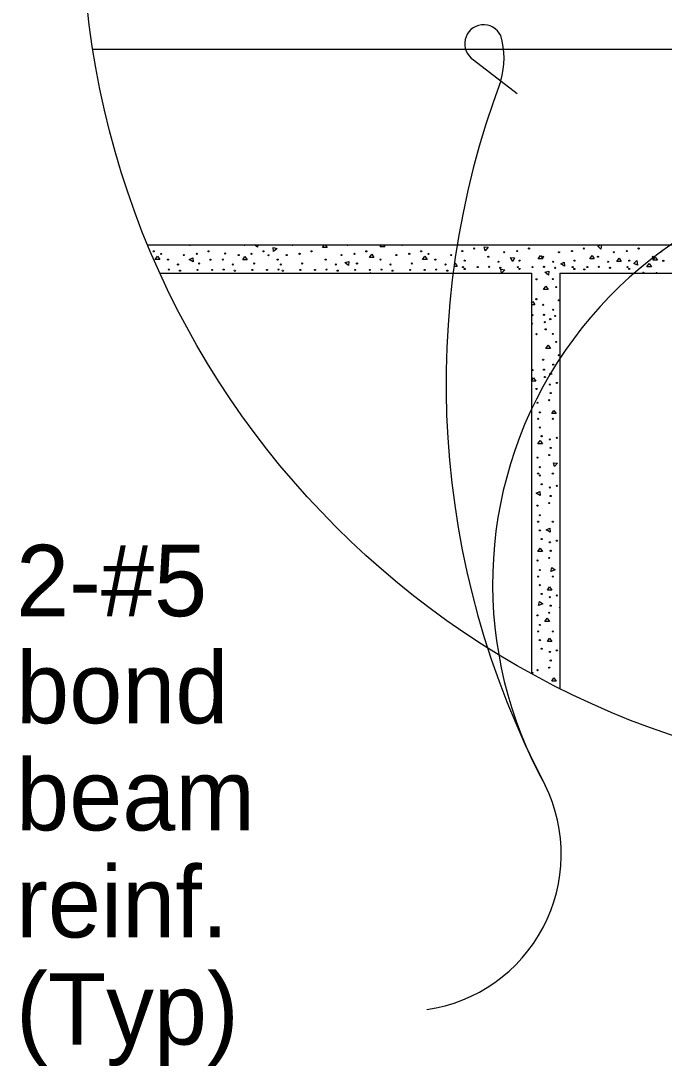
# Model space of a CAD drawing. Extents: x 0 to 2.83, y -0.03 to 1.83.
# Drawn here: x 0.6673 to 0.7845, y 0.1655 to 0.3561 of the extents above; entities that cross this region are included whole.
import ezdxf

# ---------------------------------------------------------------- set-up
doc = ezdxf.new("R2010")
doc.units = 0
for name, color, linetype in [('50', 7, 'Continuous'), ('51', 7, 'Continuous'), ('55', 7, 'Continuous'), ('57', 7, 'Continuous')]:
    doc.layers.add(name, color=color, linetype=linetype)

msp = doc.modelspace()

# ---------------------------------------------------------------- linework, layer by layer
at = {"layer": '50'}
for p, q in [((0.6903703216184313, 0.3153115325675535), (0.8714627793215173, 0.3153115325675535)), ((0.6926287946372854, 0.3101031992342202), (0.7603516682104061, 0.3101031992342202)), ((0.7655600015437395, 0.3101031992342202), (0.8714627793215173, 0.3101031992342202))]:
    msp.add_line(p, q, dxfattribs=at)
at = {"layer": '51'}
msp.add_line((0.8436961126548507, 0.35089625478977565), (0.680379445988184, 0.35089625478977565), dxfattribs=at)
at = {"layer": '55'}
for p, q in [((0.7498127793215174, 0.349004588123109), (0.7577627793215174, 0.342879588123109)), ((0.7603516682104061, 0.3101031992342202), (0.7603516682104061, 0.23710464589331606)), ((0.7655600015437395, 0.3101031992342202), (0.7655600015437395, 0.23437025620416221))]:
    msp.add_line(p, q, dxfattribs=at)
for points in [[(0.7104353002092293, 0.3153115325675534), (0.7103938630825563, 0.31485357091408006), (0.7098481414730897, 0.3153115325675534)], [(0.7133317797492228, 0.3140681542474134), (0.7132659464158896, 0.3147947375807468), (0.7139701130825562, 0.31460382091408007), (0.7133317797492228, 0.3140681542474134)], [(0.7222735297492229, 0.3147827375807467), (0.7226414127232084, 0.3153115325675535)], [(0.7227389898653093, 0.3153115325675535), (0.7231069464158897, 0.3147827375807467), (0.7222735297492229, 0.3147827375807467)], [(0.7327846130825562, 0.3149469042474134), (0.7330382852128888, 0.3153115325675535)], [(0.7333643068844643, 0.3153115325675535), (0.7336180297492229, 0.3149469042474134), (0.7327846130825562, 0.3149469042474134)], [(0.751910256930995, 0.31420630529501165), (0.7517193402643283, 0.3149103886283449), (0.7524460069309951, 0.31484472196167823), (0.751910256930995, 0.31420630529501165)], [(0.7730096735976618, 0.3145155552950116), (0.772492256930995, 0.3150299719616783), (0.7731008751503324, 0.3153115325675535)], [(0.7731500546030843, 0.3153115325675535), (0.7730096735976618, 0.3145155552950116)], [(0.6917425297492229, 0.31260657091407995), (0.6921591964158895, 0.3132054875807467), (0.6925759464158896, 0.31260657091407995), (0.6917425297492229, 0.31260657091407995)], [(0.6979428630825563, 0.31262565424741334), (0.6986031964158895, 0.3129359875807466), (0.6986646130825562, 0.31220890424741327), (0.6979428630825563, 0.31262565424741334)], [(0.7076991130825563, 0.31256023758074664), (0.708115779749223, 0.31315915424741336), (0.7085325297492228, 0.31256023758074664), (0.7076991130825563, 0.31256023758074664)], [(0.7308100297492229, 0.31297732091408), (0.7312266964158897, 0.31357623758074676), (0.7316434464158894, 0.31297732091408), (0.7308100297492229, 0.31297732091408)], [(0.7405036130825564, 0.31260657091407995), (0.740920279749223, 0.3132054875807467), (0.7413370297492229, 0.31260657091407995), (0.7405036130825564, 0.31260657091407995)], [(0.7565218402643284, 0.3129520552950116), (0.7572489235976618, 0.3128907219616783), (0.7569385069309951, 0.31223030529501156), (0.7565218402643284, 0.3129520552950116)], [(0.7615936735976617, 0.3127538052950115), (0.7620103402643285, 0.3133527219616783), (0.7624270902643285, 0.3127538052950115), (0.7615936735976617, 0.3127538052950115)], [(0.7709875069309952, 0.31273472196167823), (0.7714041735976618, 0.313333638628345), (0.7718209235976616, 0.31273472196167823), (0.7709875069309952, 0.31273472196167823)], [(0.7759133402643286, 0.31226722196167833), (0.7763300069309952, 0.31286613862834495), (0.776746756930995, 0.31226722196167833), (0.7759133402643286, 0.31226722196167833)], [(0.782518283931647, 0.31246162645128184), (0.7829349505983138, 0.31306054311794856), (0.7833517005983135, 0.31246162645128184), (0.782518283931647, 0.31246162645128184)], [(0.7263296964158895, 0.31204207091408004), (0.7270338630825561, 0.31223298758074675), (0.7269681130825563, 0.31150632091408), (0.7263296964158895, 0.31204207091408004)], [(0.7463142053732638, 0.311770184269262), (0.7464180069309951, 0.31191938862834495), (0.746834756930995, 0.31132047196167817), (0.7462487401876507, 0.31132047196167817)], [(0.7549161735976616, 0.3101426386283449), (0.7547872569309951, 0.3108607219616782), (0.7555055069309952, 0.31073197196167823), (0.7549161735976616, 0.3101426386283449)], [(0.7656861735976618, 0.3117917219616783), (0.766346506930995, 0.31210205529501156), (0.7664079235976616, 0.31137505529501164), (0.7656861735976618, 0.3117917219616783)], [(0.779715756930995, 0.31159338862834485), (0.7790535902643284, 0.31189980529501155), (0.7795710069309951, 0.3124141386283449), (0.779715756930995, 0.31159338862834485)], [(0.7814083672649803, 0.31128704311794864), (0.781825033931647, 0.31188595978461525), (0.7822417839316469, 0.31128704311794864), (0.7814083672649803, 0.31128704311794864)], [(0.7309030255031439, 0.3101031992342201), (0.7309416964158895, 0.3102492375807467), (0.7311489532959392, 0.3101031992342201)], [(0.7628104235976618, 0.3103012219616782), (0.7635145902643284, 0.3104921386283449), (0.7634488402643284, 0.30976547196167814), (0.7628104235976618, 0.3103012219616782)], [(0.7625669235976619, 0.3071603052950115), (0.7629835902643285, 0.30775922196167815), (0.7634003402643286, 0.3071603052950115), (0.7625669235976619, 0.3071603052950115)], [(0.7603516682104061, 0.304624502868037), (0.7605819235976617, 0.30495547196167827), (0.7609986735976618, 0.30435655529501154), (0.7603516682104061, 0.30435655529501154)], [(0.7603516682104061, 0.30102239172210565), (0.760553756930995, 0.3009861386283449), (0.7603516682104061, 0.300784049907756)], [(0.7629730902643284, 0.2964085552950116), (0.7633897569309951, 0.2970074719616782), (0.7638065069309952, 0.2964085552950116), (0.7629730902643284, 0.2964085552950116)], [(0.7640087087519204, 0.29183160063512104), (0.7640938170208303, 0.29170929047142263), (0.7639404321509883, 0.29170929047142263)], [(0.7603516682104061, 0.2904208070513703), (0.7607591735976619, 0.2910065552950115), (0.7611759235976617, 0.2904076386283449), (0.7603516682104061, 0.2904076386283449)], [(0.7640463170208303, 0.28450537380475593), (0.764462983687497, 0.28510429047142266), (0.7648797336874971, 0.28450537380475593), (0.7640463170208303, 0.28450537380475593)], [(0.7615225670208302, 0.278988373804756), (0.7619392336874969, 0.2795872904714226), (0.762355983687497, 0.278988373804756), (0.7615225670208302, 0.278988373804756)], [(0.7645621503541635, 0.27485529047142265), (0.7643712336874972, 0.2755594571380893), (0.7650979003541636, 0.2754937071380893), (0.7645621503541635, 0.27485529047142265)], [(0.7612004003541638, 0.2700060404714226), (0.7618607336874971, 0.270316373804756), (0.7619221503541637, 0.26958929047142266), (0.7612004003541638, 0.2700060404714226)], [(0.7630683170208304, 0.2633204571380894), (0.7637286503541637, 0.2636307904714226), (0.7637900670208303, 0.2629037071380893), (0.7630683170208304, 0.2633204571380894)], [(0.7615225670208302, 0.2593532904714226), (0.7619392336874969, 0.25995220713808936), (0.762355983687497, 0.2593532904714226), (0.7615225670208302, 0.2593532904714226)], [(0.763887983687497, 0.25574937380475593), (0.764074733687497, 0.256454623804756), (0.7646711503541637, 0.2560343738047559), (0.763887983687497, 0.25574937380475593)], [(0.7632604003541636, 0.25233245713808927), (0.7636770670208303, 0.252931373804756), (0.7640938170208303, 0.25233245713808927), (0.7632604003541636, 0.25233245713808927)], [(0.7616397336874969, 0.2495472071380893), (0.7618264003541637, 0.25025254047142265), (0.7624229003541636, 0.24983229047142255), (0.7616397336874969, 0.2495472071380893)], [(0.7654732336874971, 0.2490842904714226), (0.7655600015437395, 0.24920901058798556)], [(0.7655600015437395, 0.2490842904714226), (0.7654732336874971, 0.2490842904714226)], [(0.7628206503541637, 0.24658737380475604), (0.7632373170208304, 0.24718629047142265), (0.7636540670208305, 0.24658737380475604), (0.7628206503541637, 0.24658737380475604)], [(0.7632604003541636, 0.24294829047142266), (0.7636770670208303, 0.2435472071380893), (0.7640938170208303, 0.24294829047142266), (0.7632604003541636, 0.24294829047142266)], [(0.7603516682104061, 0.23730266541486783), (0.760619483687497, 0.23728004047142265), (0.7605003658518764, 0.2370265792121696)], [(0.7640463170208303, 0.235744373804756), (0.764462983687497, 0.23634329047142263), (0.7648797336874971, 0.235744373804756), (0.7640463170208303, 0.235744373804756)]]:
    msp.add_lwpolyline(points, dxfattribs=at)
for centre, radius in [((0.8363386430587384, 0.3755134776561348), 0.1578956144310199), ((0.7499057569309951, 0.3146187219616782), 0.00010011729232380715), ((0.7599057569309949, 0.3146187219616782), 0.00010011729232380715), ((0.7699057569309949, 0.3146187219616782), 0.00010011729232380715), ((0.779905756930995, 0.3146187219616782), 0.00010011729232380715), ((0.6914830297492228, 0.3141077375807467), 0.00010011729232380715), ((0.6928316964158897, 0.3136266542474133), 0.00010011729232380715), ((0.6940748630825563, 0.31259582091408), 0.00010011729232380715), ((0.6969669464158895, 0.3134204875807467), 0.00010011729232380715), ((0.6993231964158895, 0.3136364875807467), 0.00010011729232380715), ((0.7014830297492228, 0.3141077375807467), 0.00010011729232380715), ((0.7018161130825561, 0.3125744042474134), 0.00010011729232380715), ((0.7040748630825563, 0.31259582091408), 0.00010011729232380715), ((0.7044871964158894, 0.31370757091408), 0.00010011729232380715), ((0.7069669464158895, 0.3134204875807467), 0.00010011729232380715), ((0.7093231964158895, 0.3136364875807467), 0.00010011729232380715), ((0.7114830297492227, 0.3141077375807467), 0.00010011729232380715), ((0.7124193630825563, 0.3133838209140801), 0.00010011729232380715), ((0.7140748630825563, 0.31259582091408), 0.00010011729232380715), ((0.715728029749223, 0.3134204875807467), 0.00010011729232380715), ((0.718084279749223, 0.3136364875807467), 0.00010011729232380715), ((0.7202441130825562, 0.3141077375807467), 0.00010011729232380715), ((0.7228359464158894, 0.31259582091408), 0.00010011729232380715), ((0.725728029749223, 0.3134204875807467), 0.00010011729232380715), ((0.728084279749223, 0.3136364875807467), 0.00010011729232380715), ((0.7302441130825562, 0.3141077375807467), 0.00010011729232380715), ((0.7328359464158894, 0.31259582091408), 0.00010011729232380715), ((0.735728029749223, 0.3134204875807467), 0.00010011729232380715), ((0.738084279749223, 0.3136364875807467), 0.00010011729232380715), ((0.7402441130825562, 0.3141077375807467), 0.00010011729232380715), ((0.7415927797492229, 0.3136266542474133), 0.00010011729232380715), ((0.7428359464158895, 0.31259582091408), 0.00010011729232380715), ((0.7457280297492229, 0.3134204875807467), 0.00010011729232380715), ((0.7477459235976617, 0.31414747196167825), 0.00010011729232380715), ((0.7524975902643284, 0.31310680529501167), 0.00010011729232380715), ((0.7553896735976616, 0.31393147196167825), 0.00010011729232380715), ((0.7577459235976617, 0.31414747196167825), 0.00010011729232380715), ((0.7624975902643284, 0.31310680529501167), 0.00010011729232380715), ((0.7653896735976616, 0.31393147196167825), 0.00010011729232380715), ((0.7677459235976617, 0.31414747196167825), 0.00010011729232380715), ((0.7724975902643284, 0.31310680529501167), 0.00010011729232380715), ((0.7753896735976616, 0.31393147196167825), 0.00010011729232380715), ((0.7777459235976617, 0.31414747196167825), 0.00010011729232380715), ((0.7824975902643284, 0.31310680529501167), 0.00010011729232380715), ((0.6942319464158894, 0.3107697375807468), 0.00010011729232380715), ((0.6959066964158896, 0.31169257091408), 0.00010011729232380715), ((0.6962601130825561, 0.3105734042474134), 0.00010011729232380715), ((0.6994606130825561, 0.31071082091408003), 0.00010011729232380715), ((0.6997747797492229, 0.31188890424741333), 0.00010011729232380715), ((0.7021310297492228, 0.31071082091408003), 0.00010011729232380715), ((0.7042319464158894, 0.3107697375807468), 0.00010011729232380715), ((0.7059066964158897, 0.31169257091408), 0.00010011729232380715), ((0.7062601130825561, 0.3105734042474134), 0.00010011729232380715), ((0.7094606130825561, 0.31071082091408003), 0.00010011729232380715), ((0.7097747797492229, 0.31188890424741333), 0.00010011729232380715), ((0.7121310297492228, 0.31071082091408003), 0.00010011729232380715), ((0.7142319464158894, 0.3107697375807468), 0.00010011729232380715), ((0.7146677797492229, 0.31169257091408), 0.00010011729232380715), ((0.7150211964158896, 0.3105734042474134), 0.00010011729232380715), ((0.7182216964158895, 0.31071082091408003), 0.00010011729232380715), ((0.7185358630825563, 0.31188890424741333), 0.00010011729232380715), ((0.7208921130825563, 0.31071082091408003), 0.00010011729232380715), ((0.7229930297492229, 0.3107697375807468), 0.00010011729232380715), ((0.7246677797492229, 0.31169257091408), 0.00010011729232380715), ((0.7250211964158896, 0.3105734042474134), 0.00010011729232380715), ((0.7282216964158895, 0.31071082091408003), 0.00010011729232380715), ((0.7285358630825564, 0.31188890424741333), 0.00010011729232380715), ((0.7308921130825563, 0.31071082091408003), 0.00010011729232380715), ((0.7329930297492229, 0.3107697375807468), 0.00010011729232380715), ((0.7346677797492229, 0.31169257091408), 0.00010011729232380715), ((0.7350211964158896, 0.3105734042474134), 0.00010011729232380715), ((0.7382216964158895, 0.31071082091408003), 0.00010011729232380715), ((0.7385358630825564, 0.31188890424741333), 0.00010011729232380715), ((0.7408921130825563, 0.31071082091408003), 0.00010011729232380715), ((0.7429930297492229, 0.3107697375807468), 0.00010011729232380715), ((0.7446677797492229, 0.31169257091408), 0.00010011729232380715), ((0.7450211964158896, 0.3105734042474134), 0.00010011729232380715), ((0.7478833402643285, 0.31122180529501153), 0.00010011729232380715), ((0.7481779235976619, 0.31088422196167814), 0.00010011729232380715), ((0.7481975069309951, 0.31239988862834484), 0.00010011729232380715), ((0.750553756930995, 0.31122180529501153), 0.00010011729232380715), ((0.7526546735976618, 0.3112807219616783), 0.00010011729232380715), ((0.7543294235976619, 0.31220355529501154), 0.00010011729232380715), ((0.7546828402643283, 0.311084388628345), 0.00010011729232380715), ((0.7578833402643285, 0.31122180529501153), 0.00010011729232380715), ((0.7581779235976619, 0.31088422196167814), 0.00010011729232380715), ((0.758197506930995, 0.31239988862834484), 0.00010011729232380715), ((0.760553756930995, 0.31122180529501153), 0.00010011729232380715), ((0.7626546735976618, 0.3112807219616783), 0.00010011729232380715), ((0.7643294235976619, 0.31220355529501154), 0.00010011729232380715), ((0.7646828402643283, 0.311084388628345), 0.00010011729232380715), ((0.7678833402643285, 0.31122180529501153), 0.00010011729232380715), ((0.7681779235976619, 0.31088422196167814), 0.00010011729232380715), ((0.768197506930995, 0.31239988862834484), 0.00010011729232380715), ((0.7699960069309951, 0.31079972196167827), 0.00010011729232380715), ((0.770553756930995, 0.31122180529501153), 0.00010011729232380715), ((0.7726546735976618, 0.3112807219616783), 0.00010011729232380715), ((0.7743294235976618, 0.31220355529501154), 0.00010011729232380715), ((0.7746828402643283, 0.311084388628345), 0.00010011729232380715), ((0.7778833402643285, 0.31122180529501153), 0.00010011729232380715), ((0.7781779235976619, 0.31088422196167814), 0.00010011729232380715), ((0.778197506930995, 0.31239988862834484), 0.00010011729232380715), ((0.784400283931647, 0.3123629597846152), 0.00010011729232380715), ((0.761280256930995, 0.3089993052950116), 0.00010011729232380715), ((0.7642508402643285, 0.3090385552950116), 0.00010011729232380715), ((0.7648791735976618, 0.3075855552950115), 0.00010011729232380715), ((0.7612544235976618, 0.3053766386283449), 0.00010011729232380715), ((0.7653896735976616, 0.3051704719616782), 0.00010011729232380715), ((0.7624975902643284, 0.3043458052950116), 0.00010011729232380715), ((0.7643294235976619, 0.30344255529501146), 0.00010011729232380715), ((0.760553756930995, 0.3024608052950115), 0.00010011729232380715), ((0.7626546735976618, 0.3025197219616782), 0.00010011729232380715), ((0.7628117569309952, 0.3011788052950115), 0.00010011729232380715), ((0.7637992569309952, 0.3017285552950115), 0.00010011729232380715), ((0.7646828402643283, 0.3023233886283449), 0.00010011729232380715), ((0.7629541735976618, 0.29987272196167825), 0.00010011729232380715), ((0.761280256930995, 0.29899930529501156), 0.00010011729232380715), ((0.7642508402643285, 0.2990385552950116), 0.00010011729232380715), ((0.7648791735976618, 0.2975855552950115), 0.00010011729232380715), ((0.7624975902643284, 0.2943458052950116), 0.00010011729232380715), ((0.7643294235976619, 0.29344255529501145), 0.00010011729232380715), ((0.7653896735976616, 0.29517047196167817), 0.00010011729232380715), ((0.760553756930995, 0.2924608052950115), 0.00010011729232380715), ((0.7626546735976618, 0.2925197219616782), 0.00010011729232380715), ((0.7637992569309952, 0.2917285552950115), 0.00010011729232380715), ((0.7628117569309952, 0.2911788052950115), 0.00010011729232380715), ((0.7637061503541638, 0.28980762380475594), 0.00010011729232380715), ((0.7649824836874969, 0.2901022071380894), 0.00010011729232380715), ((0.761280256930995, 0.28899930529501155), 0.00010011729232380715), ((0.763863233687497, 0.2882564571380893), 0.00010011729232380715), ((0.7614481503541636, 0.286489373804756), 0.00010011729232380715), ((0.7636079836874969, 0.28696062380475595), 0.00010011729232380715), ((0.761899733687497, 0.2847417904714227), 0.00010011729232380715), ((0.7615855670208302, 0.28356370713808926), 0.00010011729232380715), ((0.7618801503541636, 0.28198712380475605), 0.00010011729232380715), ((0.764255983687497, 0.28356370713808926), 0.00010011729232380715), ((0.7622139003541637, 0.28039670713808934), 0.00010011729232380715), ((0.7649824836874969, 0.28010220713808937), 0.00010011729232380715), ((0.7637061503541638, 0.279807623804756), 0.00010011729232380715), ((0.763863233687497, 0.27825645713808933), 0.00010011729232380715), ((0.7614481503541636, 0.27648937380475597), 0.00010011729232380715), ((0.7636079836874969, 0.276960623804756), 0.00010011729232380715), ((0.761899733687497, 0.27474179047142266), 0.00010011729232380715), ((0.7615855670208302, 0.27356370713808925), 0.00010011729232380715), ((0.7618801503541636, 0.27322612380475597), 0.00010011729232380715), ((0.764255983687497, 0.27356370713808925), 0.00010011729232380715), ((0.7622139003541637, 0.27163570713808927), 0.00010011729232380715), ((0.7637061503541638, 0.2710466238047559), 0.00010011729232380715), ((0.7649824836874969, 0.2713412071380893), 0.00010011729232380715), ((0.763863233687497, 0.26949545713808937), 0.00010011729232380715), ((0.7614481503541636, 0.2677283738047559), 0.00010011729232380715), ((0.7636079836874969, 0.26819962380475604), 0.00010011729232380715), ((0.7615855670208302, 0.26480270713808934), 0.00010011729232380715), ((0.761899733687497, 0.26598079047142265), 0.00010011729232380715), ((0.764255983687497, 0.26480270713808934), 0.00010011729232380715), ((0.7618801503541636, 0.26322612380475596), 0.00010011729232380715), ((0.7622139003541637, 0.26163570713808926), 0.00010011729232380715), ((0.7637061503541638, 0.2610466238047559), 0.00010011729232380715), ((0.7649824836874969, 0.2613412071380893), 0.00010011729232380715), ((0.763863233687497, 0.25949545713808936), 0.00010011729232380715), ((0.7614481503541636, 0.2577283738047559), 0.00010011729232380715), ((0.7636079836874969, 0.25819962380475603), 0.00010011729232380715), ((0.761899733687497, 0.25598079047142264), 0.00010011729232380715), ((0.7615855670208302, 0.25480270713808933), 0.00010011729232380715), ((0.764255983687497, 0.25480270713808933), 0.00010011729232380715), ((0.7618801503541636, 0.25322612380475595), 0.00010011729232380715), ((0.7622139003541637, 0.25163570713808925), 0.00010011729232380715), ((0.7637061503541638, 0.2510466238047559), 0.00010011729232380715), ((0.7649824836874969, 0.2513412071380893), 0.00010011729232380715), ((0.7614481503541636, 0.2477283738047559), 0.00010011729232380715), ((0.7636079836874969, 0.24819962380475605), 0.00010011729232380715), ((0.763863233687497, 0.24949545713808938), 0.00010011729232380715), ((0.761899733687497, 0.24598079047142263), 0.00010011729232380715), ((0.7615855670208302, 0.24480270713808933), 0.00010011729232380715), ((0.764255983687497, 0.24480270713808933), 0.00010011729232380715), ((0.7618801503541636, 0.24322612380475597), 0.00010011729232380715), ((0.7622139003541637, 0.24163570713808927), 0.00010011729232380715), ((0.7637061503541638, 0.24104662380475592), 0.00010011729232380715), ((0.7649824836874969, 0.2413412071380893), 0.00010011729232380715), ((0.7636079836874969, 0.23819962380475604), 0.00010011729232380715), ((0.763863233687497, 0.23949545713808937), 0.00010011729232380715), ((0.7614481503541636, 0.2377283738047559), 0.00010011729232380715)]:
    msp.add_circle(centre, radius, dxfattribs=at)
for centre, radius, start, end in [((0.7516304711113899, 0.35195533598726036), 0.0034516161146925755, 25.24468333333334, 238.28830000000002), ((0.7408927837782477, 0.34931280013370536), 0.014469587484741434, 343.4589555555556, 16.521927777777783), ((0.9022419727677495, 0.29002862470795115), 0.15745536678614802, 159.49015277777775, 207.74072777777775), ((0.8282933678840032, 0.2534724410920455), 0.07501880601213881, 85.54228055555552, 209.31916666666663), ((0.6917382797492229, 0.31540357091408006), 0.00010011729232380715, 246.82471602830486, 293.17528397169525), ((0.6980272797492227, 0.31532507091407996), 0.00010011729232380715, 187.77162246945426, 352.2283775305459), ((0.7017382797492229, 0.31540357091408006), 0.00010011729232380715, 246.82471602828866, 293.1752839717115), ((0.7080272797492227, 0.31532507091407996), 0.00010011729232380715, 187.77162246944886, 352.22837753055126), ((0.7117382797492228, 0.31540357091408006), 0.00010011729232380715, 246.82471602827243, 293.17528397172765), ((0.7167883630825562, 0.31532507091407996), 0.00010011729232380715, 187.7716224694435, 352.2283775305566), ((0.7204993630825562, 0.31540357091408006), 0.00010011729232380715, 246.82471602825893, 293.1752839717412), ((0.7267883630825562, 0.31532507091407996), 0.00010011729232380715, 187.77162246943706, 352.2283775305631), ((0.7304993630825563, 0.31540357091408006), 0.00010011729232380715, 246.82471602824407, 293.175283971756), ((0.7367883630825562, 0.31532507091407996), 0.00010011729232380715, 187.7716224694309, 352.2283775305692), ((0.7404993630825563, 0.31540357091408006), 0.00010011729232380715, 246.8247160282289, 293.17528397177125), ((0.7467883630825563, 0.31532507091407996), 0.00010011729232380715, 187.77162246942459, 287.07691365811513), ((0.7841507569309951, 0.31393147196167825), 0.00010011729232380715, 80.6640560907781, 174.8013479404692), ((0.780553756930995, 0.31122180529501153), 0.00010011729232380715, 43.414038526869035, 212.05136550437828), ((0.780767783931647, 0.3101797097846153), 0.00010011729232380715, 310.16331469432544, 229.83668530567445), ((0.783163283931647, 0.3101012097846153), 0.00010011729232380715, 1.1386101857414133, 178.8613898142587), ((0.7603485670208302, 0.2823602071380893), 0.00010011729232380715, 271.7750530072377, 88.22494699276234), ((0.7603485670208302, 0.2800629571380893), 0.00010011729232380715, 271.7750530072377, 88.22494699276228), ((0.7603485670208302, 0.27130195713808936), 0.00010011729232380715, 271.7750530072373, 88.22494699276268), ((0.7603485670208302, 0.2635992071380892), 0.00010011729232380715, 271.7750530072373, 88.22494699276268), ((0.7603485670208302, 0.26130195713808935), 0.00010011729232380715, 271.7750530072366, 88.22494699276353), ((0.7603485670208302, 0.2535992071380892), 0.00010011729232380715, 271.7750530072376, 88.2249469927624), ((0.7603485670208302, 0.25130195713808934), 0.00010011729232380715, 271.77505300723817, 88.22494699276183), ((0.7603485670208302, 0.24359920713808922), 0.00010011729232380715, 271.7750530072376, 88.2249469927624), ((0.7603485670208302, 0.24130195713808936), 0.00010011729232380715, 271.7750530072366, 88.22494699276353), ((0.7371593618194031, 0.20417710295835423), 0.0286251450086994, 278.33535555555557, 26.033983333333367)]:
    msp.add_arc(centre, radius, start, end, dxfattribs=at)

# ---------------------------------------------------------------- texts
at = {"layer": '57'}
for s, p in [('2-#5', (0.666379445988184, 0.2475712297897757)), ('bond ', (0.666379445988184, 0.2280462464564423)), ('beam', (0.666379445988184, 0.2085212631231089)), ('reinf.', (0.666379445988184, 0.18899627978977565)), ('(Typ)', (0.666379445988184, 0.16947129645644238))]:
    msp.add_text(s, height=0.013016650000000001, dxfattribs=at).set_placement(p)

doc.saveas('drawing.dxf')
